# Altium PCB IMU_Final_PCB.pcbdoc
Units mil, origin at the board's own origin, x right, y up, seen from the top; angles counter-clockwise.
Board outline 1740.15 x 1447.24 mil, 2 copper layers (Top Layer, Bottom Layer); 21 components, 12 nets, 72 pads, 29 vias.
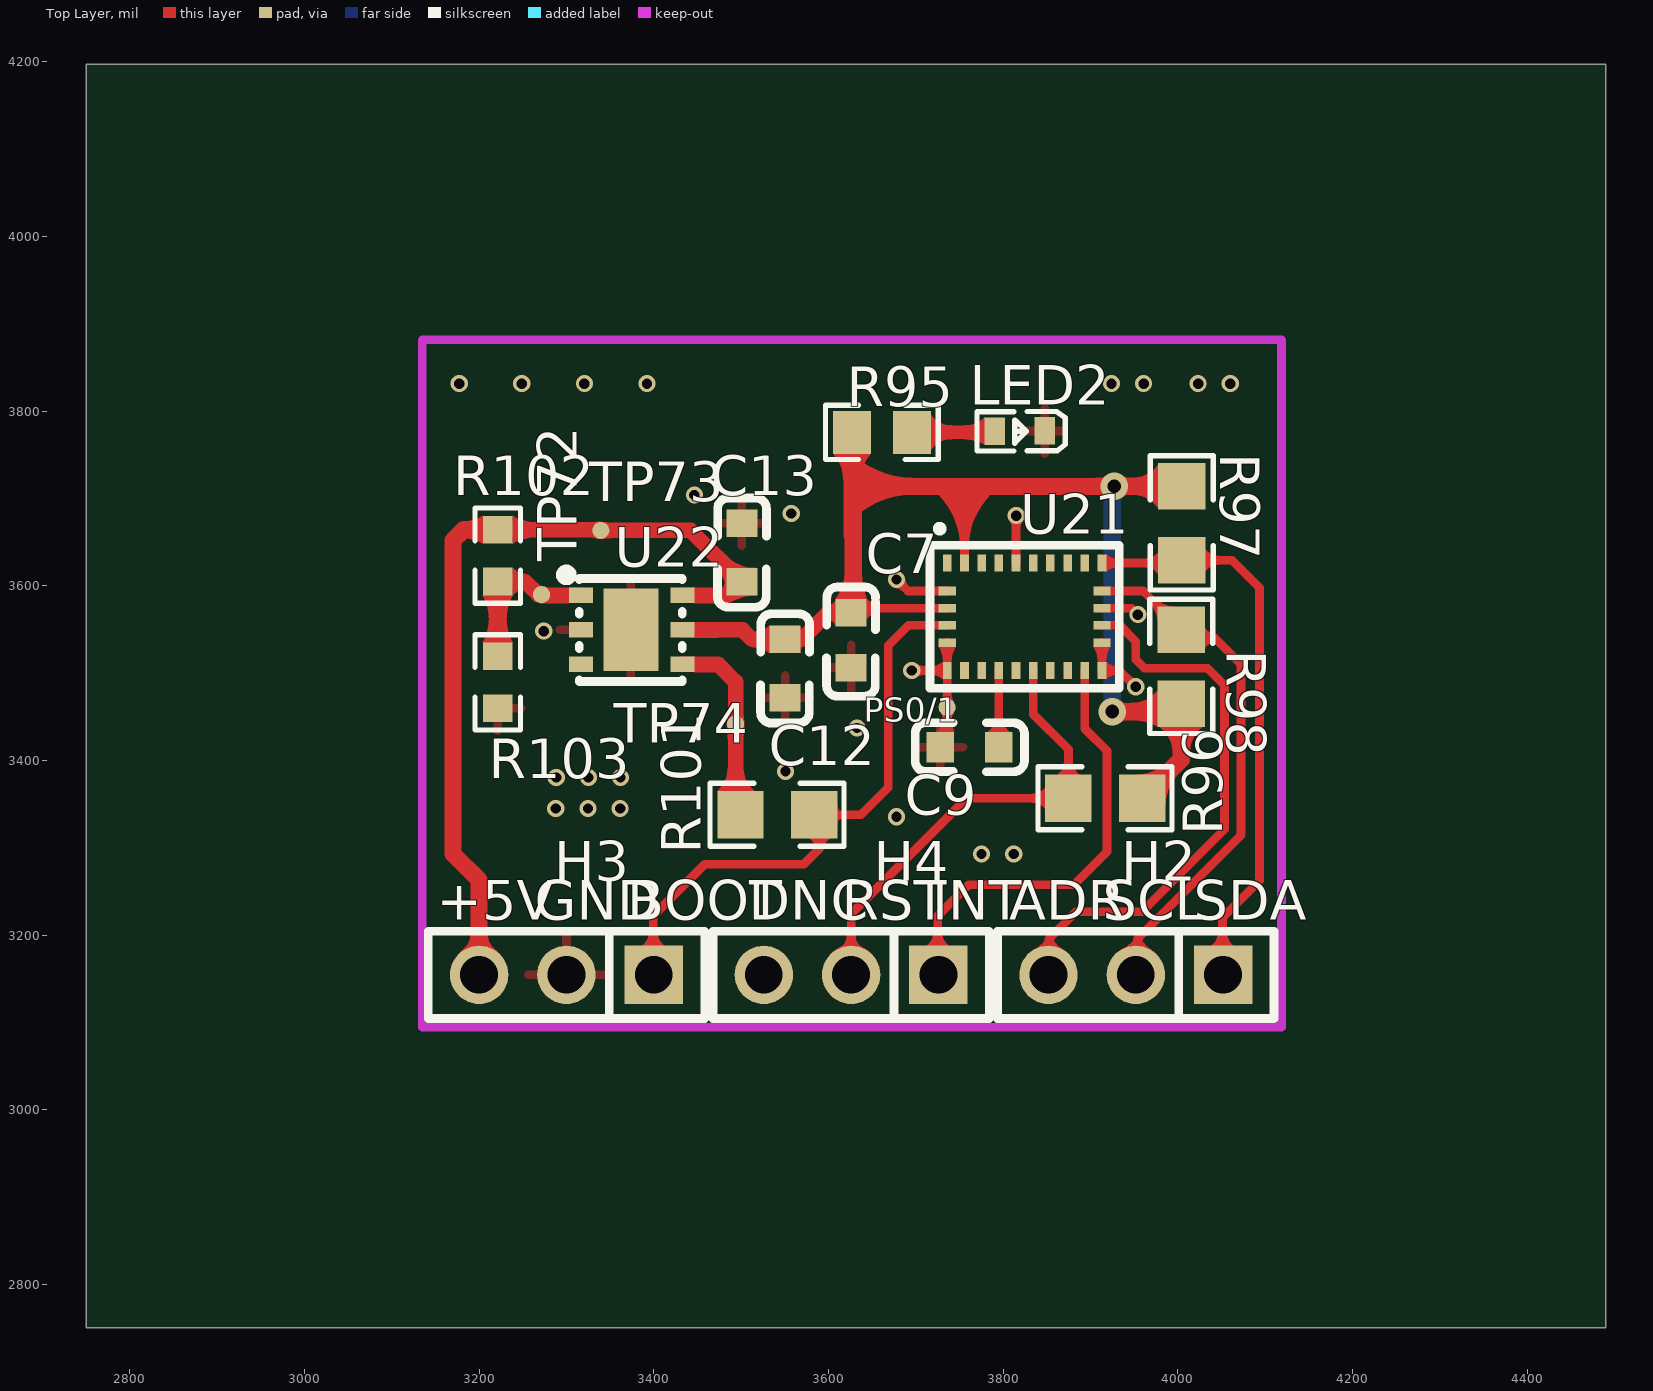
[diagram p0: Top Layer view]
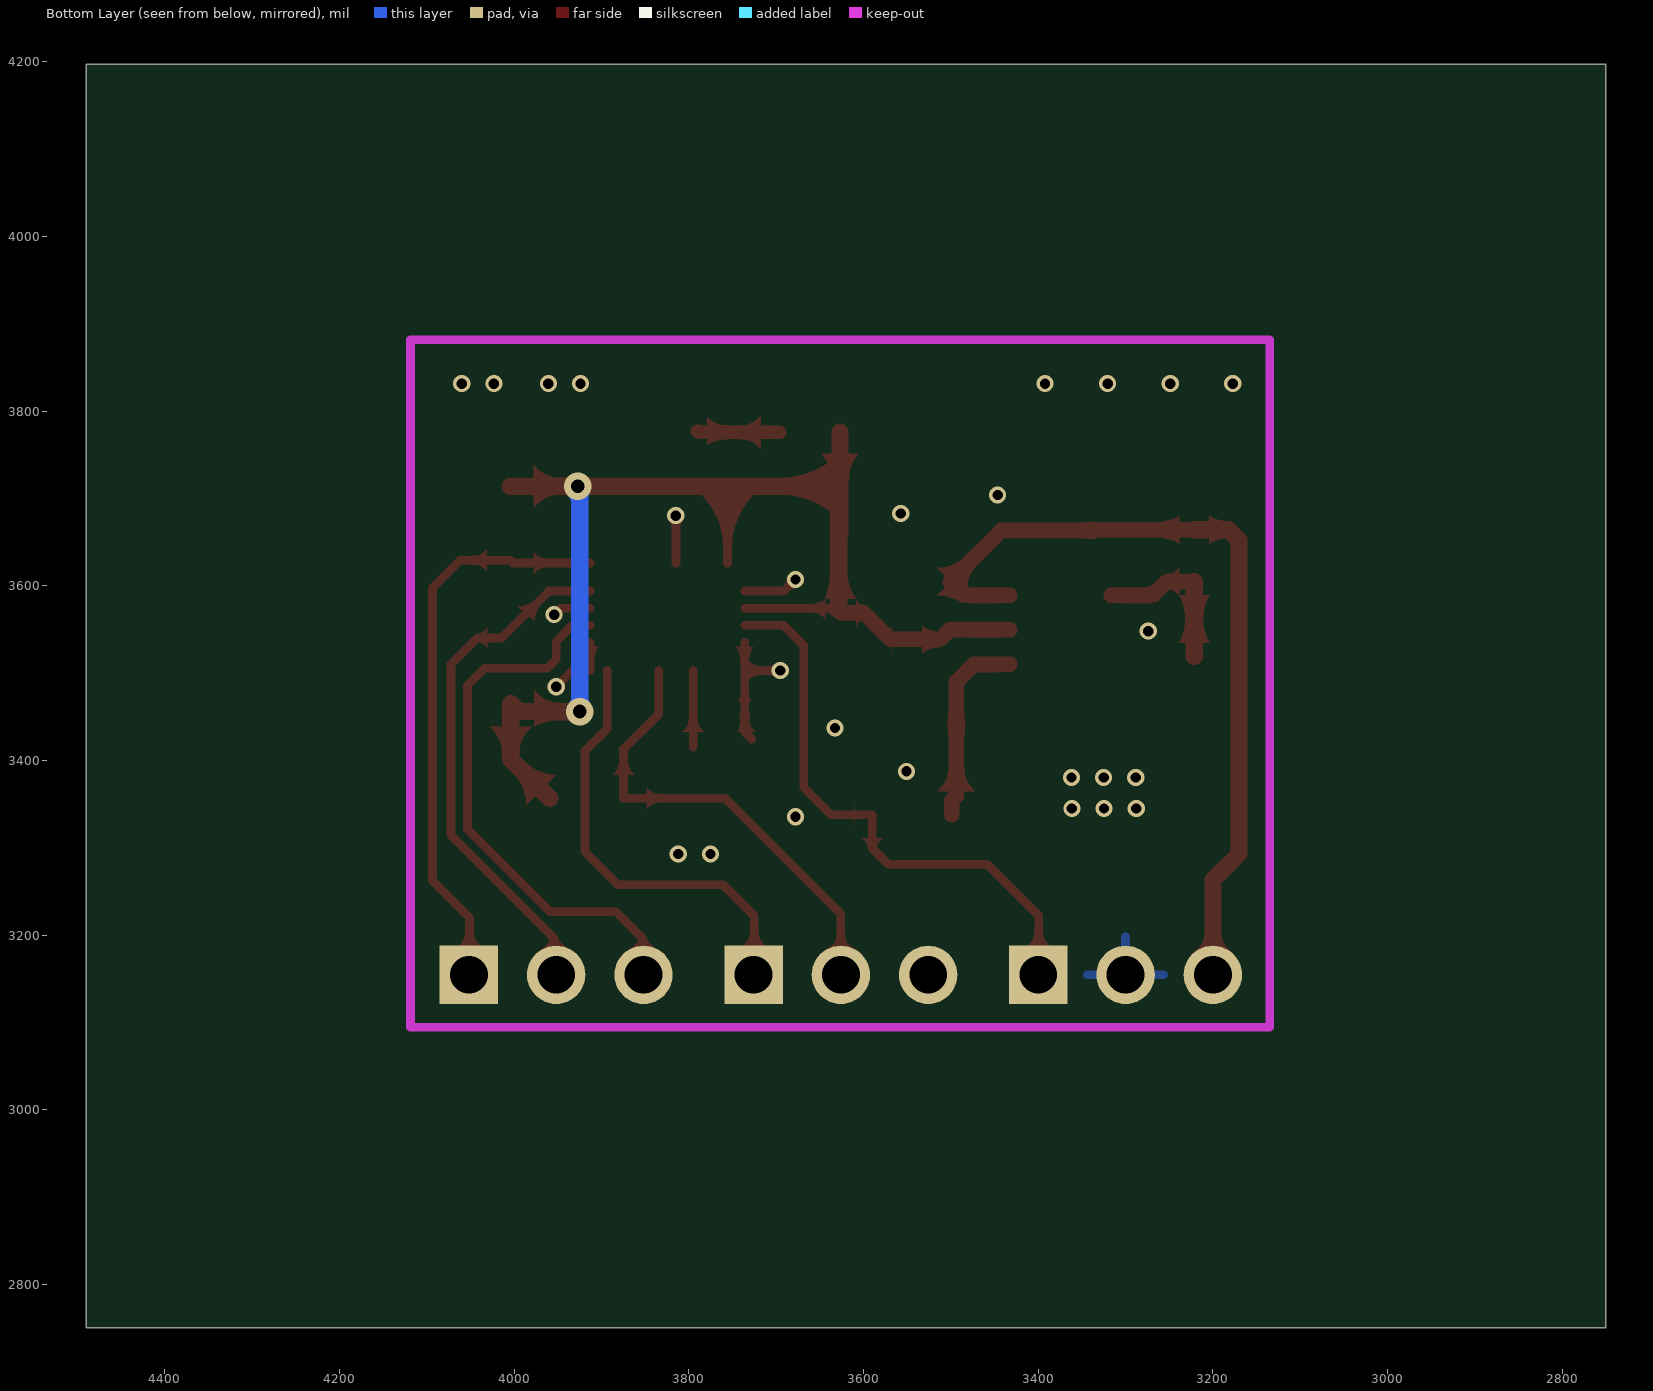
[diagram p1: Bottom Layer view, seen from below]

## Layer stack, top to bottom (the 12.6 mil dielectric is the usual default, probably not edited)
Top Layer: signal copper (thickness not stored)
Dielectric: dielectric 12.6, FR-4, Dk 4.8
Bottom Layer: signal copper (thickness not stored)

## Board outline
4490.15,2750 2750,2750 2750,4197.24 4490.15,4197.24

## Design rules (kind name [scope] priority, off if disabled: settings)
Clearance copperThickness1oz [All] p1: gap=7 ignorepadtopadclearanceinfootprint=FALSE except(4: Track-Track; 6: Track-SMDPad SMDPad-SMDPad Track-THPad SMDPad-THPad THPad-THPad Track-Via SMDPad-Via THPad-Via Via-Via SMDPad-Fill THPad-Fill Via-Fill Fill-Fill Track-Region SMDPad-Region THPad-Region Via-Region Region-Region Track-Poly SMDPad-Poly THPad-Poly Via-Poly Fill-Poly Region-Poly Poly-Poly Track-Text SMDPad-Text THPad-Text Via-Text Fill-Text Region-Text Poly-Text Text-Text; 6.9: Track-Hole SMDPad-Hole THPad-Hole Via-Hole Fill-Hole Region-Hole Poly-Hole Text-Hole Sheet-Hole; 11.8: Track-Fill Fill-Region Track-Sheet SMDPad-Sheet THPad-Sheet Via-Sheet Fill-Sheet Region-Sheet Poly-Sheet Text-Sheet)
Clearance copperThickness2oz [All] p1: gap=7 ignorepadtopadclearanceinfootprint=FALSE except(6: Track-SMDPad SMDPad-SMDPad Track-THPad SMDPad-THPad THPad-THPad Track-Via SMDPad-Via THPad-Via Via-Via SMDPad-Fill THPad-Fill Via-Fill Fill-Fill Track-Region SMDPad-Region THPad-Region Via-Region Region-Region Track-Poly SMDPad-Poly THPad-Poly Via-Poly Fill-Poly Region-Poly Poly-Poly Track-Text SMDPad-Text THPad-Text Via-Text Fill-Text Region-Text Poly-Text Text-Text; 6.9: Track-Hole SMDPad-Hole THPad-Hole Via-Hole Fill-Hole Region-Hole Poly-Hole Text-Hole Sheet-Hole; 8: Track-Track; 11.8: Track-Fill Fill-Region Track-Sheet SMDPad-Sheet THPad-Sheet Via-Sheet Fill-Sheet Region-Sheet Poly-Sheet Text-Sheet)
DiffPairsRouting differentialPair [All] p1: maxuncoupledlength=10 maxlimit=6 mostfreqgap=6 toplayer_minwidth=5 toplayer_prefwidth=10 toplayer_maxwidth=100 bottomlayer_minwidth=5 bottomlayer_prefwidth=10 bottomlayer_maxwidth=100
PasteMaskExpansion pasteMaskExpansion [All] p1:
PlaneConnect innerPlane [All] p1: planeconnectstyle=Relief reliefexpansion=20 reliefentries=4 reliefconductorwidth=10 reliefairgap=10
PolygonConnect copperRegion [All] p1: connectstyle=Relief reliefentries=4 reliefconductorwidth=10 polygonreliefangle="90 Angle" airgapwidth=10
RoutingVias viaSize [All] p1: viastyle="Through Hole" holewidth=12.0078 minholewidth=11.811 maxholewidth=248.0314 width=24.0158 minwidth=19.685 maxwidth=393.7008
SolderMaskExpansion solderMaskExpansion [All] p1: useseparateexpansions=TRUE expansion=2 expansionbottom=2
Width copperThickness1oz [All] p1: maxlimit=100 minlimit=5 preferedwidth=10
Width copperThickness2oz [All] p1: maxlimit=100 minlimit=8 preferedwidth=10

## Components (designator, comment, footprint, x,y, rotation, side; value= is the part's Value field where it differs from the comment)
C7 "CAP_0201" Cbst2 3625.98,3533.86 r90 top
C9 "CAP_0201" C9 3759.65,3415.04 r0 top
C12 "CAP_0201" C9 3550.39,3503.15 r90 top
C13 "CAP_0201" C9 3500.79,3640.16 r270 top
H2 "HDR-M_2.54_1x3P" HDR-TH_3P-P2.54-V-M 3951.97,3154.49 r180 top
H3 "HDR-M_2.54_1x3P" HDR-TH_3P-P2.54-V-M 3299.92,3154.49 r180 top
H4 "HDR-M_2.54_1x3P" HDR-TH_3P-P2.54-V-M 3625.94,3154.49 r180 top
LED2 "TLMS1100-GS08" "LED2 RED" 3822.05,3777.16 r180 top
PS0/1 "Test-Point" Test-Point-0.5mm 3735.95,3460.8 r0 top
R95 "Res_0201" Rtrip 3666.18,3775.75 r180 top
R96 "Res_0201" "0805 dany2" 3914.17,3356.69 r0 top
R97 "Res_0201" "0805 dany2" 4004.65,3674.49 r270 top
R98 "Res_0201" "0805 dany2" 4003.94,3510.24 r270 top
R101 "Res_0201" "0805 dany2" 3538.58,3337.79 r0 top
R102 "Res_0201" R0603 3221.18,3634.49 r270 top
R103 "Res_0201" R0603 3221.18,3489.49 r270 top
TP72 "Test-Point" Test-Point-0.5mm 3271.32,3589.79 r0 top
TP73 "Test-Point" Test-Point-0.5mm 3339.24,3663.45 r0 top
TP74 "Test-Point" Test-Point-0.5mm 3493.54,3441.69 r0 top
U21 "BNO055" LGA-28_L5.2-W3.8-P0.50-BL 3824.65,3564.49 r270 top
U22 "NCP708MU330TAG" DFN-6_L3.0-W3.0-P0.95-LS3.1-BL-EP 3374.65,3549.49 r270 top

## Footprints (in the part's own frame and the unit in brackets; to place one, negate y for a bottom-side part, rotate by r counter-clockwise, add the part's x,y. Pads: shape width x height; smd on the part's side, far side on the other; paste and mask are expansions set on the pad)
"0805 dany2" [mm]
  rect 1.35x1.377 smd: 1(-1,0) 2(1.15,0)
  silkscreen extent -1.89,-0.92 2.02,0.92
C9 [mm]
  rect 0.8x0.9 smd: 1(-0.8,0) 2(0.9,0)
  silkscreen extent -1.53,-0.71 1.64,0.72
Cbst2 [mm]
  rect 0.8x0.9 smd: 1(-0.7,0) 2(0.9,0)
  silkscreen extent -1.53,-0.71 1.64,0.72
DFN-6_L3.0-W3.0-P0.95-LS3.1-BL-EP [mm]
  rect 0.45x0.701 smd: 1(-1.001,-1.476) 2(0,-1.476) 3(1.001,-1.476) 4(1.001,1.476) 5(0,1.476) 6(-1.001,1.476)
  rect 2.4x1.6 smd: 7(0,-0.025)
  silkscreen extent -1.75,-2.05 1.5,1.47
HDR-TH_3P-P2.54-V-M [mm]
  rect 1.7x1.7 hole 1.1: 1(-2.54,0)
  round 1.7 hole 1.1: 2(0,0) 3(2.54,0)
  silkscreen extent -4.02,-1.27 4.02,1.27
"LED2 RED" [mm]
  rect 0.6x0.8 smd: 1(-0.65,-0.003) 2(0.8,0.003)
  silkscreen extent -1.25,-0.57 1.32,0.58
LGA-28_L5.2-W3.8-P0.50-BL [mm]
  rect 0.5x0.25 smd: 1(-1.563,-2.25) 6(1.563,-2.25) 7(1.563,-1.75) 8(1.563,-1.25) 9(1.563,-0.75) 10(1.563,-0.25) 11(1.563,0.25) 12(1.563,0.75) 13(1.563,1.25) 14(1.563,1.75) 15(1.563,2.25) 20(-1.563,2.25) 21(-1.563,1.75) 22(-1.563,1.25) 23(-1.563,0.75) 24(-1.563,0.25) 25(-1.563,-0.25) 26(-1.563,-0.75) 27(-1.563,-1.25) 28(-1.563,-1.75)
  rect 0.25x0.5 smd: 2(-0.75,-2.25) 3(-0.25,-2.25) 4(0.25,-2.25) 5(0.75,-2.25) 16(0.75,2.25) 17(0.25,2.25) 18(-0.25,2.25) 19(-0.75,2.25)
  silkscreen extent -2.66,-2.75 2.08,2.75
R0603 [mil]
  rect 31.75x34.02 smd: 1(-29.66,0) 2(29.66,0)
  silkscreen extent -55,-26 55,26
Rtrip [mm]
  rect 1.1x1.25 smd: 1(-0.753,0) 2(0.997,0)
  silkscreen extent -1.51,-0.79 1.77,0.79
Test-Point-0.5mm [mm]
  round 0.5 smd: 1(0,0)

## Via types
v1: diameter 19.68, hole 11.81, Top Layer to Bottom Layer, 27 vias
v2: diameter 31.5, hole 15.75, Top Layer to Bottom Layer, 2 vias

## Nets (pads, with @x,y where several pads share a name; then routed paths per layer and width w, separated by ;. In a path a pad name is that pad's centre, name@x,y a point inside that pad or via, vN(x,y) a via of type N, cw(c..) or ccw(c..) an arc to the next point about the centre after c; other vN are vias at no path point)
$1N1002: C9.2 U21.9 | length 87.9
  Top Layer w10: C9.2@3795.12,3415.09 U21.9
$1N2238: LED2.2 R95.1 | length 95.3
  Top Layer w15.75: R95.1 3786.93,3775.75 3788.21,3777.03 LED2.2
+5V: C13.2 H3.3 R102.1 TP73.1 U22.6 | length 944.8
  Top Layer w17.72: R102.1 3338.54,3664.15 TP73.1 3442.07,3663.45 C13.2 3484.95,3588.89 U22.6
  Top Layer w19.68: H3.3 3199.92,3263.07 3170.08,3292.91 3170.08,3651.97 3182.26,3664.15 R102.1
BOOT: H3.1 R101.2 U21.4 | length 660.8
  Top Layer w10: H3.1 3399.92,3159.21 3399.21,3159.92 3399.21,3222.05 3458.27,3281.1 3571.65,3281.1 3589.92,3299.37 3589.92,3337.79 3611.61,3337.79 ; 3612.05,3337.36 3611.61,3337.79 ; U21.4 3691.65,3554.64 3668.5,3531.5 3668.5,3369.05 3637.24,3337.79 3611.61,3337.79
EN3V3: R102.2 R103.1 TP72.1 U22.1 | length 188.5
  Top Layer w17.72: R102.2 3252.65,3604.83 3267.69,3589.79 TP72.1 TP72.1@3272.22,3588.89 ; TP72.1@3271.32,3588.89 TP72.1@3272.22,3588.89 ; U22.1 TP72.1@3272.22,3588.89
  Top Layer w19.68: R103.1 R102.2
GND: C7.1 C9.1 C12.1 C13.1 H3.2 LED2.1 PS0/1.1 R103.2 U21.2 U21.5 U21.6 U21.15 U21.16 U21.18 U21.25 U22.2 U22.7 | length 395.2
  Top Layer w10: v1(3677.95,3607.09) 3691.02,3594.01 U21.2 ; v1@3695.24,3503.15 v1(3695.43,3502.95) U21.6 ; C9.1@3728.15,3424.49 3736.06,3432.41 U21.6 ; U21.5 U21.6 ; U21.25 3814.81,3680.17 v1(3814.96,3680.31) ; U21.16 U21.15 3933.26,3502.95 v1(3951.97,3484.25) ; U21.18 3946.92,3574.33 v1(3954.33,3566.93)
  other v1: 3775.27,3292.91 3812.12,3292.91 3677.95,3335.43 3287.72,3344.88 3324.57,3344.88 3361.42,3344.88 3288.19,3380.31 3325.04,3380.31 3361.89,3380.31 3550.87,3387.4 3632.6,3437.01 3274.02,3548.03 3557.48,3682.68 3446.46,3703.94 3177.17,3831.49 3248.82,3831.49 3320.47,3831.49 3392.13,3831.49 3924.09,3831.49 3960.94,3831.49 4023.31,3831.49 4060.16,3831.49
GPIO6: H4.2 R96.1 U21.11 | length 536.5
  Top Layer w10: H4.2@3625.98,3154.53 3625.98,3224.41 3758.27,3356.69 R96.1 3874.8,3412.6 3834.49,3452.91 U21.11
I2C_ADRESS_SELECT: H2.3 U21.17 | length 640.1
  Top Layer w10: H2.3@3856.69,3155.91 3852.75,3159.84 3852.75,3196.06 3883.46,3226.77 3959.05,3226.77 4053.54,3321.26 4053.54,3486.06 4034.09,3505.51 3961.97,3505.51 3951.97,3515.51 3951.97,3536.22 3933.53,3554.65 U21.17
INT: H4.1 U21.14 | length 510.1
  Top Layer w10: H4.1 3725.94,3158.19 3725.2,3158.94 3725.2,3222.05 3760.63,3257.48 3881.1,3257.48 3918.9,3295.28 3918.9,3411.02 3893.55,3436.37 U21.14
SCK/SCL: H2.2 R98.1 U21.19 | length 599.6
  Top Layer w10: U21.19 3960.3,3594.02 4014.17,3540.16 4042.52,3540.16 4072.44,3510.24 4072.44,3314.17 3954.33,3196.06 3954.33,3156.85 H2.2
SDI/SDA: H2.1 R97.2 U21.20 | length 656
  Top Layer w10: U21.20 4001.46,3626.02 R97.2 4062.12,3629.21 4093.7,3597.64 4093.7,3262.2 4051.18,3219.68 4051.18,3155.28 H2.1
VDDIO: 
pads on no net: C7.2 C12.2 H4.3 R95.2 R96.2 R97.1 R98.2 R101.1 TP74.1 U21.1 U21.3 U21.7 U21.8 U21.10 U21.12 U21.13 U21.21 U21.22 U21.23 U21.24 U21.26 U21.27 U21.28 U22.3 U22.4 U22.5
copper on no net: | length 1738.2
  Top Layer w10: 3625.98,3569.29 3631.03,3574.33 3736.07,3574.33 ; 3755.75,3626.02 3755.75,3712 3757.6,3713.86
  Top Layer w17.72: 3432.75,3510.09 3473.62,3510.09 3493.7,3490.01 3493.7,3359.49 3499.21,3353.98 3499.21,3337.79 ; 3432.75,3549.49 3501.69,3549.49 3512.6,3538.58 3545.66,3538.58 3569.29,3538.58 3600,3569.29 3625.98,3569.29
  Top Layer w19.68: 3626.94,3775.75 3626.94,3658.09 3628.35,3656.69 ; 3631.03,3574.33 3628.35,3577.01 3628.35,3656.69 ; v2(3925.04,3455.9) 3994.88,3455.9 4003.94,3464.96 4003.94,3401.18 3959.45,3356.69 ; 4004.65,3713.86 v2(3927.41,3713.86) 3757.6,3713.86 3631.18,3713.86 3628.35,3711.02 3628.35,3656.69
  Bottom Layer w19.68: v2(3925.04,3455.9) 3925.04,3711.5 v2(3927.41,3713.86)

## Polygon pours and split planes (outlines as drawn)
no net on Top Layer (solid, remove dead copper): 3413.39,3496.06 3453.54,3496.06 3453.54,3564.57 3413.39,3564.57
GND on Top Layer (solid, remove dead copper, pour order 2): 3073.23,3056.69 4162.2,3056.69 4162.2,3911.81 3073.23,3911.81
GND on Bottom Layer (solid, remove dead copper, pour order 4): 3000,3000 4240.15,3000 4240.15,3947.24 3000,3947.24

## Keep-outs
Board Outline Layer:
  lines w10: 3134.65,3094.49 4118.9,3094.49 4118.9,3881.89 3134.65,3881.89 3134.65,3094.49

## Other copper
Top Layer:
  region: 3618.5,3614.57 3638.19,3614.57 ccw(c3720.04,3614.57) 3643.7,3585.04 3608.27,3585.04 ccw(c3570.8,3614.57)
  region: 3600,3560.43 3600,3578.15 ccw(c3600,3586.55) 3608.27,3585.04 3608.27,3553.54 ccw(c3600,3552.02)
  region: 3658.7,3579.33 3658.7,3569.33 ccw(c3658.7,3550.58) 3643.7,3561.83 3643.7,3585.04 ccw(c3658.7,3601.91)
  region net $1N1002: 3790.12,3447.76 3800.12,3447.76 ccw(c3818.87,3447.76) 3807.62,3432.76 3782.62,3432.76 ccw(c3771.37,3447.76)
  region net GND: 3731.06,3447.76 3741.06,3447.76 ccw(c3782.16,3447.76) 3743.9,3432.76 3723.56,3432.76 ccw(c3712.31,3447.76)
  region: 3512.6,3529.72 3512.6,3547.44 ccw(c3512.6,3580.12) 3532.67,3554.33 3532.67,3522.83 ccw(c3512.6,3497.04)
  region: 3569.29,3547.44 3569.29,3529.72 ccw(c3588.74,3522.83) 3568.1,3522.83 3568.1,3554.33 ccw(c3588.74,3554.33)
  region net +5V: 3473.68,3619.31 3488.18,3629.87 ccw(c3516.36,3667.45) 3516.36,3620.47 3483.08,3591.12 ccw(c3436.1,3591.12)
  region net +5V: 3491.22,3582.62 3478.69,3595.15 ccw(c3419.63,3618.33) 3483.08,3618.33 3516.36,3588.98 ccw(c3516.36,3536.04)
  region net SDI/SDA: 4046.18,3202.95 4056.18,3202.95 ccw(c4074.93,3202.95) 4063.68,3187.95 4038.68,3187.95 ccw(c4027.43,3202.95)
  region net SCK/SCL: 3949.33,3196.06 3959.33,3196.06 3959.49,3194.61 3959.95,3193.17 3960.68,3191.75 3961.64,3190.35 3964.11,3187.59 3967.09,3184.91 3973.43,3179.78 3976.23,3177.34 3978.42,3174.98 3928.66,3178.5 3931.03,3180.4 3934.07,3182.35 3940.93,3186.46 3944.15,3188.66 3946.83,3190.99 3947.86,3192.2 3948.65,3193.45 3949.15,3194.73
  region net I2C_ADRESS_SELECT: 3847.75,3196.06 3857.75,3196.06 3857.92,3194.65 3858.4,3193.27 3859.15,3191.91 3860.14,3190.57 3862.68,3187.97 3865.75,3185.45 3872.28,3180.67 3875.17,3178.4 3877.43,3176.2 3827.56,3177.38 3829.87,3179.42 3832.84,3181.53 3839.55,3185.97 3842.7,3188.33 3845.31,3190.79 3846.32,3192.06 3847.09,3193.36 3847.58,3194.7
  region net BOOT: 3394.21,3202.95 3404.21,3202.95 ccw(c3422.96,3202.95) 3411.71,3187.95 3386.71,3187.95 ccw(c3375.46,3202.95)
  region net +5V: 3190.08,3200.22 3209.76,3200.22 3209.85,3198.19 3210.1,3196.31 3210.51,3194.58 3211.06,3192.97 3211.75,3191.47 3212.55,3190.06 3214.48,3187.43 3216.77,3184.93 3219.32,3182.43 3222.05,3179.76 3224.86,3176.8 3174.98,3176.8 3177.79,3179.76 3180.52,3182.43 3183.07,3184.93 3185.36,3187.43 3187.29,3190.06 3188.1,3191.47 3188.78,3192.97 3189.33,3194.58 3189.74,3196.31 3189.99,3198.19
  region net INT: 3720.2,3202.95 3730.2,3202.95 ccw(c3748.95,3202.95) 3737.7,3187.95 3712.7,3187.95 ccw(c3701.45,3202.95)
  region net GPIO6: 3620.98,3200.25 3630.98,3200.19 3631.1,3197.59 3631.43,3195.35 3631.97,3193.43 3632.7,3191.79 3633.6,3190.38 3634.66,3189.15 3635.87,3188.06 3637.21,3187.06 3643.6,3183.04 3647.2,3180.37 3649.05,3178.71 3650.91,3176.77 3601.03,3176.83 3602.9,3178.76 3604.75,3180.42 3608.35,3183.08 3611.73,3185.19 3614.75,3187.11 3616.09,3188.11 3617.3,3189.21 3618.36,3190.44 3619.27,3191.85 3620,3193.49 3620.54,3195.41 3620.87,3197.65
  region net $1N2238: 3755.14,3767.87 3755.14,3783.62 ccw(c3755.14,3818.68) 3778.76,3792.78 3778.76,3761.28 ccw(c3755.14,3722.27)
  region net GND: 3731.06,3474.33 3741.06,3474.17 3741.22,3472.42 3741.68,3470.53 3742.41,3468.73 3743.36,3467.28 3728.69,3467.44 3729.67,3468.89 3730.42,3470.68 3730.89,3472.57
  region net GND: 3741.06,3447.43 3731.06,3447.27 3730.89,3449.03 3730.42,3450.92 3729.67,3452.71 3728.69,3454.16 3743.36,3454.32 3742.41,3452.87 3741.68,3451.07 3741.22,3449.18
  region: 3636.79,3721.61 3617.1,3721.61 ccw(c3574.29,3721.61) 3605.29,3751.14 3648.6,3751.14 ccw(c3679.6,3721.61)
  region net $1N2238: 3741.12,3783.62 3741.12,3767.87 ccw(c3741.12,3738.35) 3717.49,3756.06 3717.49,3795.43 ccw(c3741.12,3813.15)
  region: 3983.07,3394.24 3996.46,3379.79 ccw(c4038.22,3348.47) 3986.02,3348.47 3951.76,3383.8 ccw(c3951.76,3436)
  region net GPIO6: 3869.8,3398.8 3879.8,3398.8 ccw(c3898.55,3398.8) 3887.3,3383.8 3862.3,3383.8 ccw(c3851.05,3398.8)
  region net GPIO6: 3833.23,3351.69 3833.23,3361.69 ccw(c3833.23,3380.44) 3848.23,3369.19 3848.23,3344.19 ccw(c3833.23,3332.94)
  region net SDI/SDA: 3962.54,3621.02 3962.54,3631.02 ccw(c3962.54,3649.77) 3977.54,3638.52 3977.54,3613.52 ccw(c3962.54,3602.27)
  region net SDI/SDA: 4046.75,3634.21 4046.75,3624.21 ccw(c4046.75,3605.46) 4031.75,3616.71 4031.75,3641.71 ccw(c4046.75,3652.96)
  region: 3948.01,3704.02 3948.01,3723.7 ccw(c3948.01,3760.61) 3977.54,3738.46 3977.54,3689.25 ccw(c3948.01,3667.11)
  region: 4013.78,3408.86 3994.09,3408.86 ccw(c3957.18,3408.86) 3979.33,3438.38 4028.54,3438.38 ccw(c4050.69,3408.86)
  region: 3947.3,3446.06 3947.3,3465.75 ccw(c3947.3,3502.66) 3976.83,3480.51 3976.83,3438.38 ccw(c3947.3,3385.44)
  region net SCK/SCL: 3971.53,3575.73 3979.92,3581.48 ccw(c3995.83,3602.7) 3995.83,3576.18 3976.83,3559.82 ccw(c3950.31,3559.82)
  region net SCK/SCL: 4042.52,3545.16 4042.52,3535.16 ccw(c4042.52,3522.63) 4031.04,3527.66 4031.04,3552.66 ccw(c4042.52,3557.69)
  region net BOOT: 3594.92,3299.37 3584.92,3299.37 ccw(c3572.63,3299.37) 3577.42,3310.69 3602.42,3310.69 ccw(c3607.21,3299.37)
  region net BOOT: 3611.61,3342.79 3611.61,3332.79 ccw(c3634.81,3325.29) 3610.43,3325.29 3610.43,3350.29 ccw(c3634.81,3350.29)
  region: 3484.84,3391.48 3502.56,3391.48 ccw(c3535.78,3391.48) 3515.85,3364.9 3472.64,3364.9 ccw(c3449.81,3391.48)
  region net EN3V3: 3252.65,3613.69 3252.65,3595.97 ccw(c3252.65,3577.56) 3238.19,3588.95 3238.19,3620.7 ccw(c3252.65,3632.1)
  region net EN3V3: 3231.02,3559.43 3211.34,3559.43 ccw(c3146.92,3559.43) 3204.17,3588.95 3238.19,3588.95 ccw(c3295.44,3559.43)
  region net +5V: 3264.76,3673.01 3264.76,3655.29 ccw(c3264.76,3601.46) 3238.19,3648.27 3238.19,3680.02 ccw(c3264.76,3726.84) 3264.76,3673.01
  region net +5V: 3182.26,3654.31 3182.26,3673.99 ccw(c3182.26,3716.81) 3204.17,3680.02 3204.17,3648.27 ccw(c3182.26,3611.49)
  region net EN3V3: 3211.34,3564.55 3231.02,3564.55 ccw(c3295.44,3564.55) 3238.19,3535.02 3204.17,3535.02 ccw(c3146.92,3564.55)
  region net EN3V3: 3253.92,3591.03 3266.27,3603.74 3268.77,3600.98 3270.1,3600.05 3270.92,3599.76 3271.9,3599.62 3261.52,3588.88 3261.2,3589.72 3260.51,3590.14 3259.54,3590.29 3258.39,3590.27 3255.93,3590.24 3254.82,3590.47
  region net EN3V3: 3284.04,3597.75 3284.04,3580.03 3277.22,3579.89 3273.53,3579.86 3270.42,3579.99 3272.22,3599.59 3275.48,3599.11 3278.12,3598.5 3280.77,3597.97
  region net +5V: 3351.05,3672.31 3351.05,3654.59 3346.85,3654.44 3343.31,3654.1 3339.24,3653.61 3339.24,3673.29 3343.31,3672.8 3346.85,3672.46
  region net +5V: 3326.73,3655.29 3326.73,3673.01 3333.34,3673.25 3336.69,3673.36 3339.94,3673.27 3338.54,3653.63 3335.06,3654.07 3332.64,3654.62 3330.23,3655.09
  region: 3484.84,3453.66 3502.56,3453.35 3502.7,3449.84 3503.01,3447.44 3503.3,3445.05 3503.38,3441.54 3483.7,3441.85 3483.92,3445.36 3484.31,3447.76 3484.68,3450.15
  region: 3502.56,3425.12 3484.84,3424.8 3484.68,3429.78 3484.32,3433.17 3483.94,3436.56 3483.7,3441.54 3503.38,3441.85 3503.31,3436.88 3503.02,3433.48 3502.71,3430.09
  region net GND: 3741.07,3515.04 3731.07,3515.04 ccw(c3705.42,3515.04) 3726.23,3530.04 3745.91,3530.04 ccw(c3766.72,3515.04)
  region net GND: 3716.14,3497.95 3716.14,3507.95 ccw(c3716.14,3533.61) 3731.14,3512.8 3731.14,3493.11 ccw(c3716.14,3472.3)
  region net GND: 3933.15,3507.95 3933.15,3497.95 ccw(c3933.15,3472.3) 3918.15,3493.11 3918.15,3512.8 ccw(c3933.15,3533.61)
  region net GND: 3918.23,3515.04 3908.23,3515.04 ccw(c3882.58,3515.04) 3903.39,3530.04 3923.07,3530.04 ccw(c3943.88,3515.04)
  region net SDI/SDA: 3933.15,3631.02 3933.15,3621.02 ccw(c3933.15,3595.37) 3918.15,3616.18 3918.15,3635.87 ccw(c3933.15,3656.68)
  region net EN3V3: 3276.17,3580.03 3276.17,3597.75 3302.75,3597.75 3302.75,3580.03
  region: 3473.12,3518.95 3473.12,3501.23 3446.55,3501.23 3446.55,3518.95
  region: 3473.12,3558.35 3473.12,3540.63 3446.55,3540.63 3446.55,3558.35
  region net +5V: 3473.12,3597.75 3473.12,3580.03 3446.55,3580.03 3446.55,3597.75
  region: 3905.88,3704.02 3905.88,3723.7 3909.02,3723.58 3911.82,3723.54 3913.13,3723.69 3914.41,3724.05 3915.66,3724.66 3916.91,3725.6 3916.91,3702.12 3915.66,3703.05 3914.41,3703.67 3913.13,3704.02 3911.82,3704.18 3909.02,3704.14
  region: 3948.93,3723.7 3948.93,3704.02 3945.79,3704.14 3942.99,3704.18 3941.68,3704.02 3940.4,3703.67 3939.15,3703.05 3937.9,3702.12 3937.9,3725.6 3939.15,3724.66 3940.4,3724.05 3941.68,3723.69 3942.99,3723.54 3945.79,3723.58
  region: 3946.57,3465.75 3946.57,3446.06 3943.43,3446.18 3940.63,3446.23 3939.31,3446.07 3938.04,3445.72 3936.79,3445.1 3935.54,3444.17 3935.54,3467.64 3936.79,3466.71 3938.04,3466.09 3939.31,3465.74 3940.63,3465.58 3943.43,3465.63
  region net GND: 3819.81,3666.75 3809.81,3666.97 3809.65,3668.72 3809.19,3670.61 3808.47,3672.41 3807.52,3673.86 3822.2,3673.64 3821.21,3672.2 3820.46,3670.41 3819.98,3668.51
  region net GND: 3691,3601.11 3683.93,3594.04 3682.57,3595.16 3680.9,3596.17 3679.11,3596.92 3677.4,3597.26 3687.78,3607.63 3688.12,3605.93 3688.87,3604.14 3689.87,3602.47
  region net GND: 3708.88,3507.95 3708.88,3497.95 3707.13,3497.79 3705.23,3497.32 3703.44,3496.58 3701.99,3495.62 3701.99,3510.29 3703.44,3509.32 3705.23,3508.59 3707.13,3508.12
  region: 3750.75,3644.96 ccw(c3667.39,3644.96) 3726.22,3704.02 3757.6,3713.86 3785.28,3704.02 ccw(c3844.11,3644.96) 3760.75,3644.96
  region: 3695.84,3704.02 ccw(c3695.84,3605.59) 3636.79,3684.33 3626.94,3713.86 3636.79,3743.39 ccw(c3695.84,3822.13) 3695.84,3723.7
Bottom Layer:
  region: 3934.89,3690.69 3915.2,3694.22 3915.42,3697.39 3915.69,3700.02 3915.68,3701.25 3915.48,3702.5 3915.02,3703.82 3914.23,3705.24 3937.44,3701.72 3936.34,3700.61 3935.59,3699.42 3935.12,3698.16 3934.87,3696.81 3934.8,3693.9
  region: 3915.2,3477.43 3934.89,3477.43 3934.76,3474.29 3934.72,3471.49 3934.88,3470.18 3935.23,3468.9 3935.85,3467.65 3936.78,3466.4 3913.31,3466.4 3914.24,3467.65 3914.85,3468.9 3915.21,3470.18 3915.37,3471.49 3915.32,3474.29

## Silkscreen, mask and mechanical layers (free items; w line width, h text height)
Top Silkscreen Layer:
  text "+5V" at 3151.18,3217.32 h45
  text "GND" at 3263.53,3217.32 h45
  text "BOOT" at 3369.79,3217.32 h45
  text "DNC" at 3508.74,3217.32 h45
  text "RST" at 3614.99,3217.32 h45
  text "INT" at 3718.85,3217.32 h45
  text "ADR" at 3806.8,3217.32 h45
  text "SCL" at 3914.26,3217.32 h45
  text "SDA" at 4018.11,3217.32 h45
